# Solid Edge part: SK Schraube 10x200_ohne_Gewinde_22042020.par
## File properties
Author: fknapp
Template: Normal.par
Last saved by: fknapp
Revision: 24
Application: Solid Edge
Username: fknapp
Material: Aluminium
Genauigkeit: 0,99
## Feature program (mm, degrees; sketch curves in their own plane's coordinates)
sketch for "unnamed RevolvedProtrusion 1" plane through (0, 0, 0) normal (0, 0, 1) x-axis (1, 0, 0)
  line (0, 54) -> (9, 54)
  line (9, 54) -> (9, 53)
  line (9, 53) -> (5, 49)
  line (5, 49) -> (5, 46.3)
  line (5, 46.3) -> (4.7548, 46.3)
  arc centre (4.7548, 44.6952) radius 1.6048 from (4.7548, 46.3) to (3.15, 44.6952) ccw
  line (3.15, 44.6952) -> (3.15, 42)
  line (3.15, 42) -> (5, 42)
  line (5, -133) -> (5, 42)
  line (0.5, -146) -> (5, -133)
  line (0, -146) -> (0.5, -146)
revolve "unnamed RevolvedProtrusion 1" add full turn 360 deg about sketch line (0, 54) -> (0, -146)
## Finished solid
Body 1: solid body, 11 faces, 10 edges, 0 vertices.
  Faces by surface: cylinder 4, plane 4, cone 2, torus 1
  Edges by curve: circle 10
Bounding box of the edges (mm; curved faces can reach further): 18.000 x 200.000 x 18.000, from (-9, -146, -9) to (9, 54, 9).
Cylindrical faces by radius (mm): R3.15 x1, R5 x2, R9 x1
Conical faces (half-angle, radius in mm at the cone's reference point): 19.0935 deg R5 x1, 45 deg R9 x1
Toroidal faces (ring radius, tube radius in mm): R4.7548 r1.6048 x1
Planar faces by outward normal: +y 2, -y 2
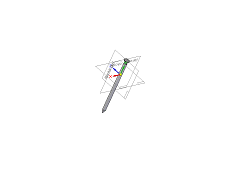
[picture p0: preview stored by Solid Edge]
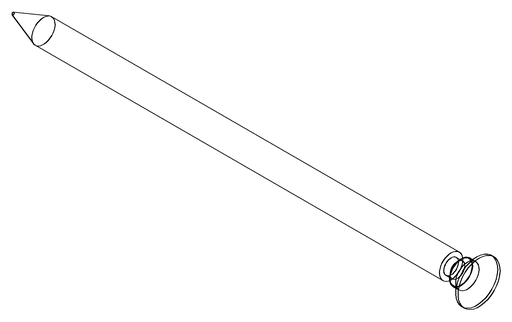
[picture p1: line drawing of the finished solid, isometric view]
